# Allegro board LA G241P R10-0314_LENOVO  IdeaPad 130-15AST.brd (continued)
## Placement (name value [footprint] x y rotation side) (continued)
PC9029  22U_0603_6.3V6M  [C_0603]  125.69 50 225 top
PC9030  22U_0603_6.3V6M  [C_0603]  90.1 62.56 270 top
PC9031  22U_0603_6.3V6M  [C_0603]  91.3 61.46 90 top
PC9033  22U_0603_6.3V6M  [C_0603]  92.57 61.46 90 top
PC9034  22U_0603_6.3V6M  [C_0603]  93.65 61.58 0 top
PC9038  22U_0603_6.3V6M  [C_0603]  93.98 60.05 0 top
PC9039  22U_0603_6.3V6M  [C_0603]  94.02 54.01 0 top
PC9040  22U_0603_6.3V6M  [C_0603]  98.36 53.95 180 top
PC9041  22U_0603_6.3V6M  [C_0603]  98.36 56.05 180 top
PC9042  22U_0603_6.3V6M  [C_0603]  98.36 57.95 180 top
PC9043  22U_0603_6.3V6M  [C_0603]  123.79 40.73 90 top
PC9044  22U_0603_6.3V6M  [C_0603]  123.79 36.86 270 top
PC9045  22U_0603_6.3V6M  [C_0603]  125 36.86 270 top
PC9056  22U_0603_6.3V6M  [C_0603]  92.97 60.02 180 top
PC9057  22U_0603_6.3V6M  [C_0603]  124.81 50.89 225 top
PC9058  22U_0603_6.3V6M  [C_0603]  128.39 47.33 225 bottom
PC9059  22U_0603_6.3V6M  [C_0603]  128.4 47.32 225 top
PC9060  22U_0603_6.3V6M  [C_0603]  126.62 49.1 225 top
PC9062  22U_0603_6.3V6M  [C_0603]  127.5 48.21 225 bottom
PC9063  22U_0603_6.3V6M  [C_0603]  126.61 49.1 225 bottom
PC9064  10U_0402_6.3V6M  [C_0402]  100.38 54.14 90 top
PC9065  10U_0402_6.3V6M  [C_0402]  101.48 52.77 270 top
PC9067  22U_0603_6.3V6M  [C_0603]  125 40.73 90 top
PC9068  22U_0603_6.3V6M  [C_0603]  123.79 36.86 270 bottom
PC9070  22U_0603_6.3V6M  [C_0603]  123.79 40.73 90 bottom
PC9071  22U_0603_6.3V6M  [C_0603]  125 36.86 270 bottom
PC9082  10U_0402_6.3V6M  [C_0402]  98.41 63.72 180 top
PC9084  220U_D2 SX_2VY_R9M  [C_D2]  130.58 54.77 0 bottom
PC9085  560U_2.5V_M  [C_OVH561M0ETR-0606]  119.79 60.2 270 bottom
PC9086  330U_D3_2.5VY_R6M  [C_D3]  125.69 60.52 90 bottom
PC9088  220U_D2 SX_2VY_R9M  [C_D2]  116 37.62 270 bottom
PC9089  220U_D2 SX_2VY_R9M  [C_D2]  120.77 37.62 270 bottom
PC11213  22U_0603_6.3V6M  [C_0603]  125 40.73 90 bottom
PC11214  0.1U_0402_16V7K  [C_0402]  146.65 31.97 180 bottom
PC11215  4.7U_0402_6.3V6M  [C_0402]  145.3 28.48 0 bottom
PC11216  10U_0805_6.3V6M  [C_0805]  146.59 33.3 180 bottom
PC11217  1U_0402_6.3V6K  [C_0402]  152.49 27.28 270 bottom
PC11224  100U_25V_NC_6.3X6  [C_6P3X6]  133.77 28.86 180 bottom
PC11225  22U_0603_6.3V6M  [C_0603]  69.62 23.46 0 top
PC11226  22U_0603_6.3V6M  [C_0603]  69.62 23.46 0 bottom
PC11227  0.1U_0402_25V6  [C_0402]  51.07 112.02 0 bottom
PD101  S SCH DIO BAS40CW SOT-323  [RB715F_SOT323-3]  25.47 16.29 270 bottom
PD501  30MA_30V_0.5UA_0.4V_SOD323-2  [D_SOD323-2]  39.15 117.82 0 top
PD703  -  [LRB715FT1G_SOT323-3]  139.32 13.31 0 bottom
PF101  7A_32VDC_0437007.WRML  [F_1206]  16.91 146.4 0 top
PF201  F1206HB12V024TM 12A 24V UL FAST  [F_1206]  108.17 26.71 0 bottom
PH201  100K +-1% 0402 B25/50 4250K  [R_0402]  98.07 66.59 270 top
PH801  100K_0402_1%_B25/50 4250K  [R_0402]  135.93 34.57 180 bottom
PH802  100K_0402_1%_B25/50 4250K  [R_0402]  145.63 49.7 270 bottom
PH803  100K_0402_1%_B25/50 4250K  [R_0402]  133.43 51.85 0 bottom
PH804  100K_0402_1%_B25/50 4250K  [R_0402]  126.14 33.94 180 bottom
PH1001  100K_0402_1%_B25/50 4250K  [R_0402]  74.46 102.14 180 bottom
PH1002  100K_0402_1%_B25/50 4250K  [R_0402]  62.51 102.98 270 bottom
PJ401  -  [JUMP_43X118]  158.33 12.26 270 bottom
PJ403  -  [JUMP_43X118]  166.21 12.77 270 bottom
PJ501  -  [JUMP_43X118]  29.62 101.42 270 bottom
PJ502  -  [JUMP_43X118]  34.83 101.42 270 bottom
PJ503  -  [JUMP_43X39]  30.52 112.87 180 bottom
PJ601  -  [JUMP_43X118]  67.72 25.64 90 bottom
PJ602  -  [JUMP_43X79]  72.99 16.56 90 top
PJ801  -  [JUMP_43X79]  77.03 9.49 180 top
PJ802  -  [JUMP_43X79]  62.7 8.92 180 top
PJ803  -  [JUMP_43X79]  53.14 5.14 90 top
PJ804  -  [JUMP_43X79]  53.56 19.42 90 top
PJ901  -  [JUMP_43X118]  41.07 154.59 0 top
PJ902  -  [JUMP_43X118]  49.01 155.16 0 bottom
PJ1000  -  [JUMP_43X39]  151.3 27.02 180 bottom
PJ1001  -  [JUMP_43X39]  150.38 34.76 0 bottom
PJP402  -  [JUMP_43X39]  161.65 20.88 0 top
PJP404  -  [JUMP_43X39]  169.56 21.94 270 top
PL101  5A_Z120_25M_0805_2P  [TAI-T_HCB2012KF-121T50_2P]  17.31 148.23 90 top
PL102  5A_Z120_25M_0805_2P  [TAI-T_HCB2012KF-121T50_2P]  19.15 148.23 90 top
PL201  5A_Z120_25M_0805_2P  [TAI-T_HCB2012KF-121T50_2P]  112.4 27.97 0 bottom
PL202  5A_Z120_25M_0805_2P  [TAI-T_HCB2012KF-121T50_2P]  112.4 26.19 0 bottom
PL301  1UH_2.8A_30%_4X4X2_F  [L_4X4X2_F_2P]  131.73 24.35 270 bottom
PL401  5A_Z120_25M_0805_2P  [5A_Z120_0805_2P]  153.42 23.59 0 bottom
PL402  1.5UH_6A_20%_5X5X3_M  [L_5X5X3_M]  157.99 19.76 270 bottom
PL403  5A_Z120_25M_0805_2P  [5A_Z120_0805_2P]  162.84 28.57 270 bottom
PL404  1.5UH_6A_20%_5X5X3_M  [L_5X5X3_M]  166.07 20.26 270 bottom
PL501  5A_Z120_25M_0805_2P  [5A_Z120_0805_2P]  38.61 100.93 0 bottom
PL502  1UH_11A_20%_7X7X3_M  [L_7X7X3_M]  32.41 106.47 0 bottom
PL602  1UH_6.6A_20%_5X5X3_M  [L_5X5X3_M_2P]  68.67 16.67 90 bottom
PL700  4.7UH_5.5A_20%_7X7X3_M  [L_7X7X3_M_2P]  129 12.75 90 bottom
PL801  -  [5A_Z80_0805_2P]  137.21 26.07 180 bottom
PL802  -  [5A_Z80_0805_2P]  137.21 24.29 180 bottom
PL803  0.24UH_22A_+-20%_ 7X7X3_M  [L_7X7X3_M]  137.06 47.59 180 bottom
PL804  0.24UH_22A_+-20%_ 7X7X3_M  [L_7X7X3_M]  133.57 38.32 180 bottom
PL901  1UH_6.6A_20%_5X5X3_M  [L_5X5X3_M_2P]  44.78 148.22 90 bottom
PL1001  0.24UH_22A_+-20%_ 7X7X3_M  [L_7X7X3_M]  70.04 106.37 0 bottom
PL1002  -  [5A_Z80_0805_2P]  64.12 112.93 180 bottom
PQ501  -  [AON7408L_DFN8-5]  38.76 104.74 180 top
PQ502  -  [AON7506_DFN3X3-8-5]  39.65 106.65 90 top
PQ704  -  [AON7408L_DFN8-5]  136.77 18.52 180 bottom
PQ705  -  [AON7506_DFN33-8-5]  125.8 20.95 180 bottom
PQ706  -  [AON7752_DFN3X3EP8-5]  137.65 16.61 270 bottom
PQ707  -  [2N7002KW_SOT323-3]  30.67 156.44 270 top
PQ710  -  [LMUN5113T1G_SOT323-3]  124.57 12.43 270 bottom
PQ711  -  [LTC015EUBFS8TL_UMT3F]  120.74 11.55 0 bottom
PQ712  -  [AON7506_DFN33-8-5]  28.05 154.42 270 top
PQ740  -  [EMB04N03H_EDFN5X6-8-5]  25.93 152.86 90 top
PQ741  -  [L2N7002WT1G_SC70-3]  141.76 11.41 180 bottom
PQ801  -  [AON6380_DFN5X6-8-5]  145.9 51.21 90 bottom
PQ802  AON6314_N_DFN56-8-5  [Q_N_DFN56-8-5]  143.92 47.08 180 bottom
PQ803  -  [AON6380_DFN5X6-8-5]  137.57 34.44 0 bottom
PQ804  AON6314_N_DFN56-8-5  [Q_N_DFN56-8-5]  141.89 40.29 270 bottom
PQ1001  -  [AON6962_DFN5X6D-8-7]  63.4 110.31 0 bottom
PR107  45.3K_0603_1%  [R_0603]  22.38 15.4 90 bottom
PR108  1.5K_0603_5%  [R_0603]  21.17 15.52 180 bottom
PR109  1K_0603_5%  [R_0603]  21.17 16.79 180 bottom
PR201  100_0402_1%  [R_0402]  110.71 29.56 90 top
PR202  100_0402_1%  [R_0402]  109.88 29.56 90 top
PR203  200K_0402_1%  [R_0402]  112.93 29.56 90 top
PR204  200K_0402_1%  [R_0402]  112.11 29.56 90 top
PR205  10K_0402_5%  [R_0402]  113.76 29.56 90 top
PR206  16.5K_0402_1%  [R_0402]  159.84 64.23 0 top
PR401  0_0402_5%  [R0402_0OHM]  156.21 22.9 270 bottom
PR402  499K_0402_1%  [R_0402]  161.32 27.92 270 bottom
PR403  1K_0402_1%  [R_0402]  162.92 22.83 180 top
PR404  150K_0402_1%  [R_0402]  160.49 27.01 90 bottom
PR405  4.7_1206_5%  [R_1206]  156.68 23.4 270 top
PR406  100K_0402_5%  [R_0402]  159.51 28.01 270 bottom
PR407  1K_0402_1%  [R_0402]  171.06 26.81 90 bottom
PR408  0_0402_5%  [R0402_0OHM]  165.41 23.64 270 bottom
PR409  4.7_1206_5%  [R_1206]  165.06 20.73 0 top
PR410  2.2K_0402_5%  [R_0402]  167.67 36.3 270 top
PR411  0_0402_5%  [R0402_0OHM]  166.91 36.3 270 top
PR412  1M_0402_1%  [R_0402]  162 24.6 0 top
PR451  560K_0402_5%  [R_0402]  164.73 30.45 0 top
PR452  105K_0402_1%  [R_0402]  165.65 31.27 180 top
PR501  2.2_0603_5%  [R_0603]  38.51 110.96 180 bottom
PR502  12.7K_0402_1%  [R_0402]  40.74 114.08 180 bottom
PR503  4.7_1206_5%  [R_1206]  36.79 110.52 0 top
PR504  5.1_0603_5%  [R_0603]  41.11 116.3 180 bottom
PR505  2.2_0603_5%  [R_0603]  41.11 116.3 180 top
PR506  6.04K_0402_1%  [R_0402]  33.49 116.63 270 bottom
PR507  470K_0402_1%  [R_0402]  38.51 115.59 90 top
PR508  0_0402_5%  [R0402_0OHM]  37.89 118.78 180 top
PR509  10K_0402_1%  [R_0402]  32.62 116.62 180 bottom
PR510  0_0402_5%  [R0402_0OHM]  36.1 118.79 270 top
PR601  1M_0402_1%  [R_0402]  63.27 20.15 90 bottom
PR603  0_0402_5%  [R0402_0OHM]  62.45 21.06 270 bottom
PR605  4.7_1206_5%  [R_1206]  72.61 15.59 90 bottom
PR606  0_0402_5%  [R0402_0OHM]  68.91 15.84 0 top
PR607  0_0402_5%  [R0402_0OHM]  62.05 19 0 top
PR608  12.1K_0402_1%  [R_0402]  62.18 16.34 0 top
PR609  0_0402_5%  [R_0402]  62.97 19.89 180 top
PR610  20K_0402_1%  [R_0402]  62.97 18.12 180 top
PR611  100K_0402_5%  [R_0402]  64.1 20.1 0 top
PR612  1K_0402_1%  [R_0402]  62.19 17.16 0 top
PR703  0.01_1206_1%  [R_1206_4P]  32.13 153.99 0 top
PR727  10K_0402_1%  [R_0402]  152.47 15.26 0 bottom
PR729  287K_0402_1%  [R_0402]  151.74 22.19 180 bottom
PR731  158K_0402_1%  [R_0402]  152.49 19.68 0 bottom
PR732  49.9K_0402_1%  [R_0402]  150.83 21.43 0 bottom
PR737  3M_0402_5%  [R_0402]  33.73 156.4 90 top
PR738  1M_0402_1%  [R_0402]  34.63 155.59 180 top
PR740  2_0402_5%  [R_0402]  149.08 22.37 270 bottom
PR741  100K_0402_1%  [R_0402]  153.41 18.79 180 bottom
PR742  2_0402_5%  [R_0402]  145.51 13.05 270 bottom
PR743  10_1206_5%  [R_1206]  142.46 14.99 180 bottom
PR745  100_0402_1%  [R_0402]  145.8 20.9 90 bottom
PR749  200K_0402_1%  [R_0402]  143.74 13.23 0 bottom
PR750  200K_0402_1%  [R_0402]  149.95 12.13 90 bottom
PR751  76.8K_0402_1%  [R_0402]  144.6 12.29 180 bottom
PR752  162K_0402_1%  [R_0402]  150.78 13.05 270 bottom
PR753  165K_0402_1%  [R_0402]  152.47 14.37 0 bottom
PR754  499_0402_1%  [R_0402]  151.6 13.51 270 bottom
PR755  38.3K_0402_1%  [R_0402]  149.06 13.05 270 bottom
PR757  100K_0402_1%  [R_0402]  144.81 15.09 270 bottom
PR760  4.7_0402_5%  [R_0402]  143.58 16.43 90 bottom
PR762  4.02K_0402_1%  [R_0402]  28.08 156.75 0 top
PR763  4.02K_0402_1%  [R_0402]  28.08 155.92 0 top
PR765  0.01_1206_1%  [R_1206_4P]  124.61 15.33 180 bottom
PR766  4.7_1206_5%  [R_1206]  133.44 12.41 0 bottom
PR769  0_0402_5%  [R0402_0OHM]  153.39 17.92 180 bottom
PR770  0_0402_5%  [R0402_0OHM]  153.39 17.04 180 bottom
PR771  0_0603_5%  [R0603_0OHM]  144.87 20.72 180 bottom
PR772  0_0402_5%  [R0402_0OHM]  149.88 22.36 270 bottom
PR776  0_0402_5%  [R0402_0OHM]  147.3 12.15 180 bottom
PR777  0_0402_5%  [R0402_0OHM]  153.39 16.15 180 bottom
PR778  10K_0402_1%  [R_0402]  148.17 13.05 270 bottom
PR779  76.8K_0402_1%  [R_0402]  143.69 11.41 0 bottom
PR780  1K_0402_1%  [R_0402]  160.05 65.17 90 top
PR801  1_0402_5%  [R_0402]  148.69 43.45 90 bottom
PR803  2.2_0603_5%  [R_0603]  150.78 45.62 180 bottom
PR804  4.7_1206_5%  [R_1206]  135.98 42.83 0 bottom
PR805  1.91K_0603_1%  [R_0603]  153.75 49.04 0 bottom
PR806  4.7_0805_5%  [R_0805]  150.69 38.7 0 top
PR807  48.7K_0402_1%  [R_0402]  154.22 47.85 180 top
PR808  0_0402_5%  [R0402_0OHM]  156.05 36.62 270 top
PR809  10K_0402_1%  [R_0402]  155.98 48.75 270 top
PR810  45.3K_0402_1%  [R_0402]  153.88 40.99 0 top
PR811  10K_0402_1%  [R_0402]  154.26 38.38 0 top
PR812  10_0402_1%  [R_0402]  155.23 36.61 180 top
PR813  100K_0402_5%  [R_0402]  152.03 47.85 0 bottom
PR814  0_0402_5%  [R0402_0OHM]  156 49.56 180 top
PR816  10_0402_1%  [R_0402]  156.94 48.75 270 top
PR818  2.2_0402_5%  [R_0402]  156.67 40.29 0 top
PR820  10_0402_1%  [R_0402]  158.27 37.29 90 top
PR821  60.4K_0402_1%  [R_0402]  155.86 38.84 270 bottom
PR823  10_0402_1%  [R_0402]  154.14 45.42 90 top
PR824  0_0402_5%  [R0402_0OHM]  157.44 38.84 270 bottom
PR825  316K_0402_1%  [R_0402]  157.51 36.62 270 bottom
PR826  0_0402_5%  [R0402_0OHM]  158.33 35.7 90 bottom
PR827  0_0402_5%  [R0402_0OHM]  153.3 49.56 0 top
PR828  24K_0402_1%  [R_0402]  156.11 36.62 270 bottom
PR829  0_0402_5%  [R0402_0OHM]  92.23 73.04 90 bottom
PR830  60.4K_0402_1%  [R_0402]  159.34 45.12 0 bottom
PR831  0_0402_5%  [R0402_0OHM]  159.08 45.18 0 top
PR832  169K_0402_1%  [R_0402]  159.92 45.99 90 top
PR833  0_0402_5%  [R0402_0OHM]  92.23 75.74 270 bottom
PR834  25.5K_0402_1%  [R_0402]  159.34 46.89 0 bottom
PR835  100K_0402_5%  [R_0402]  160.24 40.37 270 bottom
PR836  15.4K_0402_1%  [R_0402]  156.8 44.61 0 top
PR837  2.2_0402_5%  [R_0402]  158.89 41.88 0 top
PR838  0_0402_5%  [R0402_0OHM]  159.11 46 180 top
PR839  34.8K_0402_1%  [R_0402]  157.06 46.4 270 top
PR841  2.2_0603_5%  [R_0603]  150.71 39.72 180 bottom
PR842  8.45K_0402_1%  [R_0402]  159.34 41.81 0 bottom
PR843  15K_0402_1%  [R_0402]  159.34 44.29 0 bottom
PR844  4.7_1206_5%  [R_1206]  133.7 33.49 180 bottom
PR845  1.13K_0402_1%  [R_0402]  152.54 36.61 0 bottom
PR846  17.4K_0402_1%  [R_0402]  160 44.35 180 top
PR847  15K_0402_1%  [R_0402]  160.25 42.64 180 bottom
PR848  9.1K_0402_1%  [R_0402]  160 43.53 180 top
PR849  12K_0402_1%  [R_0402]  159.34 43.46 0 bottom
PR850  3.9_0402_1%  [R_0402]  157.7 43.73 270 top
PR851  0_0402_5%  [R0402_0OHM]  151.92 37.86 90 bottom
PR852  806_0402_1%  [R_0402]  156.1 48.8 0 bottom
PR853  1.13K_0402_1%  [R_0402]  154.13 37.5 0 bottom
PR901  0_0402_5%  [R0402_0OHM]  45.65 148.93 90 top
PR902  150K_0402_1%  [R_0402]  40.73 142.73 270 top
PR903  1M_0402_1%  [R_0402]  41.57 143.54 180 top
PR904  4.7_1206_5%  [R_1206]  45.37 145.38 180 bottom
PR905  22.6K_0402_1%  [R_0402]  45.7 143.1 180 top
PR906  0_0402_5%  [R_0402]  42.49 142.98 270 top
PR907  18K_0402_1%  [R_0402]  43.38 142.98 270 top
PR1001  3.9_0402_1%  [R_0402]  51.26 108.62 0 bottom
PR1002  100K_0402_1%  [R_0402]  57.7 112.32 180 top
PR1003  187K_0402_1%  [R_0402]  51.26 104.49 0 bottom
PR1004  0_0402_5%  [R0402_0OHM]  52.56 105.31 180 bottom
PR1005  0_0402_5%  [R0402_0OHM]  55.08 112.31 270 top
PR1006  4.7K_0402_1%  [R_0402]  51.06 113.76 0 bottom
PR1007  0_0402_5%  [R0402_0OHM]  49.48 106.14 0 bottom
PR1008  14.3K_0402_1%  [R_0402]  52.56 106.96 180 top
PR1009  10.5K_0402_1%  [R_0402]  51.26 106.96 0 bottom
PR1010  59K_0402_1%  [R_0402]  51.64 105.31 0 top
PR1011  10.2K_0402_1%  [R_0402]  52.17 107.79 180 bottom
PR1012  68K_0402_1%  [R_0402]  51.64 106.14 0 top
PR1013  13K_0402_1%  [R_0402]  51.64 106.14 0 bottom
PR1014  0_0402_5%  [R0402_0OHM]  56.28 103.47 0 top
PR1015  47K_0402_1%  [R_0402]  59.71 104.74 0 bottom
PR1016  4.7K_0402_1%  [R_0402]  52.17 103.66 180 bottom
PR1017  10K_0402_1%  [R_0402]  57.32 101.06 180 bottom
PR1018  0_0402_5%  [R0402_0OHM]  54.19 112.44 270 bottom
PR1019  10_0402_5%  [R_0402]  58.96 104.41 90 top
PR1020  931_0402_1%  [R_0402]  55.29 102.71 180 bottom
PR1021  0_0402_5%  [R0402_0OHM]  50.38 104.48 90 bottom
PR1022  0_0402_5%  [R0402_0OHM]  53.3 112.44 270 bottom
PR1023  300_0402_1%  [R_0402]  48.67 106.15 270 bottom
PR1024  0_0402_5%  [R0402_0OHM]  56.28 102.58 0 top
PR1025  0_0402_5%  [R0402_0OHM]  55.03 112.44 270 bottom
PR1026  34K_0402_1%  [R_0402]  49.56 105.39 270 bottom
PR1027  10_0402_5%  [R_0402]  58.94 102.58 0 top
PR1028  76.8K_0402_1%  [R_0402]  56.4 102.71 0 bottom
PR1029  4.7_0603_5%  [R_0603]  52.07 110.9 180 bottom
PR1030  1.37K_0603_1%  [R_0603]  55.08 100.42 90 bottom
PR1031  2.2_0603_5%  [R_0603]  57.27 111.12 0 bottom
PR1032  4.7_0603_5%  [R_0603]  60.8 103.66 180 bottom
PR1033  0_0603_5%  [R0603_0OHM]  59.65 106.77 0 bottom
PR1034  4.7_1206_5%  [R_1206]  70.51 101.57 180 bottom
PR1098  0_0402_5%  [R_0402]  56.78 111.51 180 top
PR1099  10K_0402_5%  [R_0402]  51.06 112.92 0 bottom
PR1458  3.24K_0402_1%  [R_0402]  146.2 29.35 90 bottom
PR1459  1K_0402_1%  [R_0402]  146.65 31.08 180 bottom
PR2001  12.7K_0402_1%  [R_0402]  65.37 8.03 270 top
PR2002  1.6K_0402_1%  [R_0402]  51.18 17.93 270 top
PR2003  0_0402_5%  [R0402_0OHM]  50.38 7.83 90 top
PR2004  3.4K_0402_1%  [R_0402]  52.94 17.94 180 top
PR2005  0_0402_5%  [R0402_0OHM]  75.66 6.24 90 top
PR2006  1M_0402_5%  [R_0402]  74.83 7.16 270 top
PR2007  10K_0402_1%  [R_0402]  65.37 6.32 270 top
PR2008  47K_0402_5%  [R_0402]  51.21 8.74 270 top
PR2009  100K_0402_5%  [R_0402]  73.07 5.17 180 top
PR2221  10_0402_1%  [R_0402]  61.36 15.37 0 top
PR2222  0_0402_1%  [R_0402]  62.27 14.55 180 top
PR2223  0_0402_5%  [R_0402]  49.57 7.83 90 top
PU401  -  [SY8286BRAC_QFN20_3X3]  157.46 23.1 0 bottom
PU402  -  [SY8286CRAC_QFN20_3X3]  166.65 23.76 0 bottom
PU501  -  [RT8207PGQW_WQFN20_3X3]  35.04 113.91 90 bottom
PU601  -  [SY8288RAC_QFN20_3X3]  67.55 16.15 180 top
PU703  S IC ISL88739AHRZ-T QFN 32P CHARGER  [ISL95520HRZ-T_QFN32_4X4]  150.22 18.39 180 bottom
PU801  -  [RT3661ABGQW_WQFN40_5X5]  152.87 45.67 270 bottom
PU901  -  [SY8286RAC_QFN20_3X3]  45.35 147.57 270 top
PU903  G2992F1U  [APL5336KAI-TRL_SOP8P8]  148.36 28.99 90 bottom
PU1001  -  [RT3662EBGQW_WQFN32_4X4]  57.54 105.38 90 bottom
PU2001  -  [G9661MF11U_SO8]  72.35 6.38 90 top
PU2002  -  [G9661MF11U_SO8]  50.75 10.23 0 top
Q19  ME4856-G_SO8  [AO4430L_SO8]  69.6 34.41 180 top
Q83  2N7002KW_SOT323-3  [L2N7002WT1G_SC-70-3]  60.61 29.81 0 top
Q84  -  [2N7002KW_SOT323-3]  63.27 29.81 180 top
Q201  -  [PJ2301_SOT23-3]  26.04 143.6 270 top
Q401  -  [2N7002KDW_SOT363-6]  59.82 4.46 90 top
Q411  -  [2N7002K_SOT23-3]  29.17 114.75 0 top
Q412  -  [2N7002K_SOT23-3]  33.17 114.75 0 top
QC1  -  [LBSS139WT1G_SC70-3]  93.06 71.4 0 top
QC2  PJT138KA_SOT363-6  [DMN66D0LDW-7_SOT363-6]  82.96 86.28 270 bottom
QC17  -  [PJT138KA_SOT363-6]  90.39 27.73 270 bottom
QC18  AO3416L_SOT23-3  [AO3416_SOT23-3]  151.03 28.31 180 top
QC19  AO3416L_SOT23-3  [AO3416_SOT23-3]  151.03 33.01 180 top
QC20  AO3416L_SOT23-3  [AO3416_SOT23-3]  155.03 28.31 180 top
QC21  AO3416L_SOT23-3  [AO3416_SOT23-3]  155.03 33.01 180 top
QC22  2N7002KDW_SOT-363-6  [DMN66D0LDW-7_SOT363-6]  145.45 25.42 90 bottom
QH5  -  [MMBT3904_NL_SOT23-3]  24.6 110.23 0 bottom
QH15  2N7002KDW 2N SC88-6  [2N7002DW-T-R7_SOT363-6]  19.49 107.46 90 bottom
QH17  -  [2N7002KW_SOT323-3]  18.19 98.16 180 top
QV1  L2N7002SDW1T1G 2N SOT-363  [2N7002KDWH_SOT363-6]  87.8 147.92 270 top
QV11  -  [2N7002KW_SOT323-3]  83.09 107.79 0 top
QV16  -  [PJ2301_SOT23-3]  102.39 103.5 180 top
QV17  -  [2N7002KW_SOT323-3]  99.38 104.61 90 top
QV18  -  [2N7002KW_SOT323-3]  97.56 102.68 180 top
QV21  L2N7002DW1T1G 2N SOT-363  [2N7002KDW_SOT363-6]  82.5 111.18 0 top
R189  0_0603_5%  [R0603_0OHM]  177.7 46.39 180 top
R192  47K_0402_5%  [R_0402]  176.1 67.21 0 top
R194  10K_0402_5%  [R_0402]  159.51 61.22 180 top
R198  10K_0402_5%  [R_0402]  160.94 54.31 90 top
R201  150K_0402_5%  [R_0402]  30.61 144 270 top
R202  100K_0402_5%  [R_0402]  33.54 145.89 0 top
R203  0_0805_5%  [R0805_0OHM]  37.34 151.61 0 top
R204  0_0402_5%  [R0402_0OHM]  25.21 146.74 90 top
R205  100K_0402_5%  [R_0402]  24.39 146.74 90 top
R207  0_0402_5%  [R0402_0OHM]  26.94 149.19 0 top
R209  100K_0402_5%  [R_0402]  26.94 150.02 0 top
R210  100K_0402_5%  [R_0402]  24.35 145.93 0 top
R211  0_0805_5%  [R0805_0OHM]  30.06 149.42 90 top
R212  0_0603_5%  [R0603_0OHM]  25.19 141.47 180 top
R214  10K_0402_5%  [R_0402]  180.05 62.02 270 top
R233  0_0805_5%  [R0805_0OHM]  176.2 21.95 0 bottom
R242  0_0805_5%  [R0805_0OHM]  163.26 40.95 0 top
R243  0_0402_5%  [R0402_0OHM]  173.7 42.33 270 top
R244  0_0402_5%  [R0402_0OHM]  174.53 42.33 270 top
R245  0_0402_5%  [R0402_0OHM]  175.41 42.33 270 top
R246  0_0402_5%  [R0402_0OHM]  175.73 34.11 90 bottom
R247  0_0402_5%  [R0402_0OHM]  177.5 42.63 0 top
R248  0_0402_5%  [R0402_0OHM]  177.5 43.46 0 top
R249  0_0402_5%  [R_0402]  176.62 34.11 90 bottom
R250  0_0402_5%  [R0402_0OHM]  177.5 41.81 0 top
R251  100K_0402_5%  [R_0402]  172.94 41.41 90 top
R271  0_0402_5%  [R_0402]  131.87 63.47 180 top
R272  470_0402_5%  [R_0402]  157.55 56.27 180 top
R273  100K_0402_5%  [R_0402]  9.31 156.63 90 top
R274  470_0402_5%  [R_0402]  132.74 63.54 270 top
R275  0_0402_5%  [R0402_0OHM]  150.82 62.12 270 top
R276  0_0402_5%  [R0402_0OHM]  151.6 62.12 270 top
R277  470_0402_5%  [R_0402]  152.89 62.13 270 top
R278  0_0402_5%  [R0402_0OHM]  131.87 62.64 180 top
R279  0_0805_5%  [R0805_0OHM]  172.85 22.47 270 bottom
R280  4.7K_0402_5%  [R_0402]  174.18 21.89 270 bottom
R283  0_0402_5%  [R0402_0OHM]  157.55 57.03 180 top
R301  0_0402_5%  [R_0402]  22.62 66.96 0 bottom
R364  16.5K_0402_1%  [R_0402]  118.26 12.17 270 bottom
R365  16.5K_0402_1%  [R_0402]  158.66 64.74 180 top
R366  100K +-1% 0402 B25/50 4250K  [R_0402]  119.09 11.26 90 bottom
R367  100K +-1% 0402 B25/50 4250K  [R_0402]  49.61 117.38 0 bottom
R368  16.5K_0402_1%  [R_0402]  127.92 43.6 270 bottom
R369  100K +-1% 0402 B25/50 4250K  [R_0402]  128.74 42.69 90 bottom
R371  0_0603_5%  [R0603_0OHM]  104.07 97.27 180 bottom
R376  200_0402_1%  [R_0402]  7.22 136.62 0 bottom
R377  412_0402_1%  [R_0402]  31.07 3.84 0 top
R378  200_0402_1%  [R_0402]  7.22 137.44 0 bottom
R420  0_0805_5%  [R0805_0OHM]  182.65 64.83 270 top
R428  0_0402_5%  [R0402_0OHM]  180.11 64.72 90 top
R921  10_0402_5%  [R_0402]  180.42 55.53 0 top
R922  0_0402_5%  [R0402_0OHM]  166.12 47.16 180 top
R923  0_0402_5%  [R0402_0OHM]  166.91 47.27 270 top
R929  0_0402_5%  [R0402_0OHM]  165.2 46.39 0 top
R930  4.7K_0402_5%  [R_0402]  168.75 44.75 0 top
R931  10K_0402_5%  [R_0402]  167.9 47.24 270 top
R932  0_0402_5%  [R0402_0OHM]  174.45 46.51 0 top
R933  470_0402_5%  [R_0402]  29.87 112.03 90 top
R934  100K_0402_5%  [R_0402]  33.7 118.52 180 top
R935  470_0603_5%  [R_0603]  68.13 36.37 180 top
R937  0_0402_5%  [R0402_0OHM]  87.01 29.37 0 top
R940  0_0402_5%  [R0402_0OHM]  91.84 31.65 0 top
R941  0_0402_5%  [R_0402]  87.01 30.19 0 top
R944  100K_0402_5%  [R_0402]  144.49 26.27 270 bottom
R945  100K_0402_1%  [R_0402]  57.11 6.01 270 top
R946  22_0603_1%  [R_0603]  59.84 8.22 270 top
R947  4.7K_0402_5%  [R_0402]  62.75 31.02 0 top
R948  100K_0402_5%  [R_0402]  160.24 49.87 90 top
R949  100K_0402_5%  [R_0402]  163.11 47.99 0 top
R950  0_0402_5%  [R0402_0OHM]  117.8 46.69 90 bottom
R951  0_0402_5%  [R0402_0OHM]  116.91 46.69 90 bottom
RA2  0_0805_5%  [R0805_0OHM]  13.21 15.78 0 bottom
RA6  0_0603_5%  [R0603_0OHM]  2.4 22.78 270 bottom
RA23  200K_0402_1%  [R_0402]  7.36 29.72 90 bottom
RA31  BLM15BD121SN1D_2P  [MURAT_BLM15BD121SN1D_2P]  19.71 49.1 270 bottom
RA36  4.7K_0402_5%  [R_0402]  18.24 44.54 0 bottom
RA41  47K_0402_5%  [R_0402]  9.35 36.73 0 bottom
RA42  BLM15BD121SN1D_2P  [MURAT_BLM15BD121SN1D_2P]  16.41 47.32 270 bottom
RA43  10K_0402_5%  [R_0402]  16.72 15.59 0 bottom
RA44  10K_0402_5%  [R_0402]  17.44 45.37 180 bottom
RA45  47_0402_5%  [R_0402]  19.95 43.65 0 bottom
RA46  0_0402_5%  [R0402_0OHM]  16.72 16.41 0 bottom
RA47  27K_0402_5%  [R_0402]  9.48 33.75 0 bottom
RA48  0_0603_5%  [R0603_0OHM]  17.38 29.8 315 bottom
RA49  4.7K_0402_5%  [R_0402]  17.44 44.54 180 bottom
RA50  33_0402_5%  [R_0402]  5.4 23.76 180 bottom
RA51  100K_0402_1%  [R_0402]  6.61 30.08 180 bottom
RA52  33_0402_5%  [R_0402]  4.96 25.95 180 bottom
RA53  0_0402_5%  [R0402_0OHM]  13.17 18.39 270 bottom
RA54  2.2K_0402_5%  [R_0402]  9.14 30.63 270 bottom
RA55  47K_0402_5%  [R_0402]  9.35 35.91 0 bottom
RA56  47_0402_5%  [R_0402]  16.53 43.74 0 bottom
RA57  10K_0402_5%  [R_0402]  18.24 45.37 0 bottom
RA58  2.2K_0402_5%  [R_0402]  8.25 30.63 270 bottom
RA59  0_0603_5%  [R0603_0OHM]  3.65 19.84 180 bottom
RA60  0_0402_5%  [R0402_0OHM]  4.46 29.09 0 bottom
RA61  0_0402_5%  [R0402_0OHM]  13.57 52.53 270 bottom
RA62  33K_0402_5%  [R_0402]  16.65 48.16 0 bottom
RA63  0_0402_5%  [R0402_0OHM]  19.76 37.9 180 bottom
RA64  0_0402_5%  [R0402_0OHM]  18.24 42.77 0 bottom
RA65  0_0402_5%  [R0402_0OHM]  21.24 49.76 225 top
RA66  0_0402_5%  [R0402_0OHM]  4.46 28.22 0 bottom
RC1  196_0402_1%  [R_0402]  102.58 55.26 90 top
RC2  196_0402_1%  [R_0402]  105.43 55.15 0 top
RC3  39.2_0402_1%  [R_0402]  78.02 53.56 180 bottom
RC4  1K_0402_5%  [R_0402]  77.1 57.82 0 bottom
RC13  300_0402_5%  [R_0402]  96.42 75.42 270 bottom
RC14  300_0402_5%  [R_0402]  89.94 76.31 270 top
RC16  150_0402_1%  [R_0402]  95.23 65.88 180 top
RC17  2K_0402_1%  [R_0402]  96.36 68.92 90 bottom
RC18  2.2K_0402_5%  [R_0402]  94.13 79.77 90 bottom
RC20  0_0402_5%  [R0402_0OHM]  94.77 73.11 90 bottom
RC21  4.7K_0402_5%  [R_0402]  95.15 83.42 270 top
RC22  100K_0402_5%  [R_0402]  93.69 68.31 270 top
RC24  4.7K_0402_5%  [R_0402]  93.23 80.61 0 top
RC25  1K_0402_5%  [R_0402]  92.42 67.45 90 top
RC26  1K_0402_5%  [R_0402]  92.42 66.59 270 top
RC27  33_0402_5%  [R_0402]  84.13 80.92 90 top
RC30  0_0402_5%  [R_0402]  79.72 88.54 90 bottom
RC34  2.2K_0402_5%  [R_0402]  112.37 51.85 180 bottom
RC35  2.2K_0402_5%  [R_0402]  107.23 53.43 180 top
RC36  1K_0402_5%  [R_0402]  113.68 53.24 0 bottom
RC38  15K_0402_5%  [R_0402]  112.37 51.02 180 bottom
RC39  15K_0402_5%  [R_0402]  114.59 52.42 180 bottom
RC40  15K_0402_5%  [R_0402]  105.56 53.89 270 top
RC41  10K_0402_5%  [R_0402]  98.96 28.53 90 top
RC44  10K_0402_5%  [R_0402]  112.37 52.99 180 bottom
RC45  10K_0402_5%  [R_0402]  107.23 54.26 180 top
RC46  10K_0402_5%  [R_0402]  114.59 50 180 bottom
RC49  10K_0402_5%  [R_0402]  105.63 34.24 90 bottom
RC52  10K_0402_5%  [R_0402]  105.63 37.76 270 bottom
RC53  10K_0402_5%  [R_0402]  104.8 37.76 270 bottom
RC54  10K_0402_5%  [R_0402]  104.8 35.16 270 bottom
RC59  0_0402_5%  [R0402_0OHM]  114.4 47.53 180 bottom
RC60  47K_0402_5%  [R_0402]  114.4 46.77 180 bottom
RC63  4.7K_0402_5%  [R_0402]  110.07 42.84 270 bottom
RC64  0_0402_5%  [R0402_0OHM]  110.9 42.84 270 bottom
RC66  0_0402_5%  [R0402_0OHM]  110.7 48.62 90 bottom
RC69  10K_0402_5%  [R_0402]  107.23 52.61 180 top
RC71  33_0402_5%  [R_0402]  85.18 32.43 270 bottom
RC73  0_0402_5%  [R0402_0OHM]  83.92 32.42 180 bottom
RC75  10K_0402_5%  [R_0402]  93.88 37.19 270 bottom
RC76  2K_0402_5%  [R_0402]  93.88 35.48 270 bottom
RC77  10K_0402_5%  [R_0402]  91.71 37.56 0 bottom
RC78  2K_0402_5%  [R_0402]  92.62 38.38 180 bottom
RC79  10K_0402_5%  [R_0402]  93.88 39.07 90 bottom
RC80  2K_0402_5%  [R_0402]  93.06 35.48 270 bottom
RC81  10K_0402_5%  [R_0402]  107.23 51.78 180 top
RC82  2K_0402_5%  [R_0402]  105.56 51.99 270 top
RC83  10K_0402_5%  [R_0402]  106.58 47.39 90 top
RC84  2K_0402_5%  [R_0402]  105.63 48.28 90 top
RC85  10K_0402_5%  [R_0402]  110.58 51.86 270 bottom
RC86  2K_0402_5%  [R_0402]  113.68 51.66 0 bottom
RC87  20M_0402_5%  [R_0402]  110.52 39.29 270 bottom
RC88  1K_0402_1%  [R_0402]  100.43 44.76 180 top
RC89  1K_0402_1%  [R_0402]  99.51 48.12 270 top
RC90  10K_0402_5%  [R_0402]  87.91 36.78 90 top
RC93  33_0402_5%  [R_0402]  89.5 36.4 90 bottom
RC94  100K_0402_5%  [R_0402]  88.79 34.57 0 bottom
RC100  1K_0402_1%  [R_0402]  105.62 55.97 0 top
RC101  1K_0402_1%  [R_0402]  102.66 48.48 180 top
RC102  33_0402_5%  [R_0402]  101.64 22.95 180 bottom
RC103  1M_0402_5%  [R_0402]  110.71 64.81 270 bottom
RC104  33_0402_5%  [R_0402]  110.72 65.56 180 bottom
RC105  33_0402_5%  [R_0402]  109.88 64.11 270 bottom
RC108  11.8K_0402_1%  [R_0402]  103.91 47.58 90 top
RC111  0_0402_5%  [R0402_0OHM]  101.89 35.15 180 top
RC112  10K_0402_5%  [R_0402]  111.67 53.94 180 bottom
RC113  10K_0402_5%  [R_0402]  99.91 35.16 270 top
RC120  0_0402_5%  [R0402_0OHM]  92.9 38.12 90 top
RC129  0_0201_5%  [R0201_0OHM]  99.98 38.93 270 bottom
RC130  0_0201_5%  [R0201_0OHM]  100.61 38.93 270 bottom
RC133  10K_0402_5%  [R_0402]  86.27 36.48 180 top
RC134  10K_0402_5%  [R_0402]  86.27 35.65 180 top
RC144  2.2K_0402_5%  [R_0402]  87.77 25.43 0 bottom
RC145  2.2K_0402_5%  [R_0402]  90.4 25.43 180 bottom
RC146  2.2K_0402_5%  [R_0402]  89.49 28.8 0 bottom
RC147  2.2K_0402_5%  [R_0402]  88.62 28.8 180 bottom
RC150  1K_0402_5%  [R_0402]  146.22 24.35 180 top
RC151  1K_0402_5%  [R_0402]  148 24.35 180 top
RC152  100K_0402_5%  [R_0402]  148.29 26.07 0 bottom
RC153  100K_0402_5%  [R_0402]  146.6 24.41 180 bottom
RC156  10K_0402_5%  [R_0402]  108.27 41.04 270 top
RC157  10K_0402_5%  [R_0402]  108.27 38.42 90 top
RC158  10K_0402_5%  [R_0402]  111.67 55.08 180 bottom
RC159  10K_0402_5%  [R_0402]  111.67 55.91 180 bottom
RC160  10K_0402_5%  [R_0402]  94.91 39.91 180 top
RC161  10K_0402_5%  [R_0402]  94.91 39.08 180 top
RC162  2.2K_0402_5%  [R_0402]  82.18 36.86 0 bottom
RC163  2.2K_0402_5%  [R_0402]  81.38 36.86 180 bottom
RC164  0_0402_5%  [R_0402]  97.94 40.85 270 bottom
RD201  1K_0402_5%  [R_0402]  29.27 61.53 270 top
RD202  10K_0402_5%  [R_0402]  32.54 25.06 270 top
RD203  10K_0402_5%  [R_0402]  31.14 25.06 270 top
RD204  10K_0402_5%  [R_0402]  25.34 44.45 0 bottom
RD205  0_0402_5%  [R0402_0OHM]  32.59 23.33 0 top
RD206  0_0402_5%  [R0402_0OHM]  31.14 23.35 270 top
RD207  0_0402_5%  [R0402_0OHM]  26.25 45.27 180 bottom
RD208  1K_0402_1%  [R_0402]  26.25 49.04 90 bottom
RD209  1K_0402_1%  [R_0402]  25.35 48.23 0 bottom
RD210  0_0402_5%  [R0402_0OHM]  38.7 54.27 270 top
RH27  2.2K_0402_5%  [R_0402]  16.72 108.55 0 top
RH28  2.2K_0402_5%  [R_0402]  16.72 107.73 0 top
RH29  4.7K_0402_5%  [R_0402]  23.84 108.89 270 top
RH30  4.7K_0402_5%  [R_0402]  23.08 108.89 270 top
RH133  150K_0402_5%  [R_0402]  25.63 111.98 180 bottom
RH137  100K_0402_5%  [R_0402]  24.15 106.39 0 bottom
RH138  200K_0402_5%  [R_0402]  22.94 111.98 0 bottom
RL1  0_0603_5%  [R0603_0OHM]  38 137.51 90 top
RL4  0_0402_5%  [R0402_0OHM]  11.52 138.09 270 bottom
RL5  0_0402_5%  [R0402_0OHM]  10.63 138.09 270 bottom
RL6  0_0402_5%  [R0402_0OHM]  9.49 114.83 90 bottom
RL7  0_0402_5%  [R0402_0OHM]  10.31 114.83 90 bottom
RL8  1K_0402_5%  [R_0402]  31.7 138.85 0 top
RL9  2.49K_0402_1%  [R_0402]  38.08 133.76 180 bottom
RL10  15K_0402_5%  [R_0402]  32.62 138.02 180 top
RL11  0_0603_5%  [R_0603]  37.99 139.17 90 bottom
RL17  10K_0402_5%  [R_0402]  35.79 136.86 90 top
RL18  0_0603_5%  [R0603_0OHM]  40.22 132.75 180 bottom
RL19  75_0805_5%  [R_0805]  20.03 135.26 90 top
RP3  2.2K_0804_8P4R_5%  [RP_0804_8P4R]  160.5 57.76 180 top
RP4  100K_0804_8P4R_5%  [RP_0804_8P4R]  169.33 41.94 90 top
RPC1  1K_0804_8P4R_5%  [RP_0804_8P4R]  86.44 74.07 90 bottom
RPC2  1K_0804_8P4R_5%  [RP_0804_8P4R]  96.15 74.14 270 top
RPC3  1K_0804_8P4R_5%  [RP_0804_8P4R]  86.72 91.53 90 top
RPC4  1K_0804_8P4R_5%  [RP_0804_8P4R]  83.16 91.53 90 top
RPC5  10K_0804_8P4R_5%  [RP_0804_8P4R]  86.34 80.42 90 top
RPC6  33_0804_8P4R_5%  [RP_0804_8P4R]  108.54 33.11 90 bottom
RPC9  1K_0804_8P4R_5%  [RP_0804_8P4R]  107.04 37.12 270 bottom
RPC11  10K_0804_8P4R_5%  [RP_0804_8P4R]  95.66 24.43 0 bottom
RPC12  10K_0804_8P4R_5%  [RP_0804_8P4R]  87.65 36.16 90 bottom
RPC13  10K_0804_8P4R_5%  [RP_0804_8P4R]  89.07 36.86 90 top
RPC14  1K_0804_8P4R_5%  [RP_0804_8P4R]  90.84 76.35 180 bottom
RPH1  499_0804_8P4R_1%  [RP_0804_8P4R]  17.41 104.98 0 top
RPH2  499_0804_8P4R_1%  [RP_0804_8P4R]  17.41 101.62 0 top
RPV34  10K_8P4R_5%  [RP_0804_8P4R]  84.3 149.45 270 bottom
RR1  6.19K_0402_1%  [R_0402]  29.99 9.11 0 top
RR5  0_0402_5%  [R0402_0OHM]  23.14 9.19 270 top
RV1  1.69K_0402_1%  [R_0402]  91.74 128.16 270 top
RV2  1K_0402_1%  [R_0402]  87.37 139.67 270 top
RV3  1K_0402_1%  [R_0402]  92.75 128.16 270 top
RV4  100K_0402_5%  [R_0402]  103.28 126.09 270 bottom
RV5  47K_0402_5%  [R_0402]  90.56 147.33 270 top
RV6  47K_0402_5%  [R_0402]  88.26 145.49 0 top
RV8  8.45K_0402_1%  [R_0402]  97.24 133.03 270 top
RV9  2K_0402_1%  [R_0402]  96.39 132.12 90 top
RV11  8.45K_0402_1%  [R_0402]  99.04 130.68 90 top
RV12  2K_0402_1%  [R_0402]  98.14 131.58 270 top
RV13  4.75K_0402_1%  [R_0402]  99.04 133.75 270 top
RV15  8.45K_0402_1%  [R_0402]  103.11 128.57 0 bottom
RV16  4.75K_0402_1%  [R_0402]  103.14 129.48 0 bottom
RV17  1K_0402_5%  [R_0402]  84.1 146.86 270 top
RV20  1M_0402_5%  [R_0402]  103.22 121.56 90 bottom
RV21  10K_0402_5%  [R_0402]  89.69 148.76 270 bottom
RV28  8.45K_0402_1%  [R_0402]  100.11 132.5 90 top
RV29  10K_0402_5%  [R_0402]  94.8 127.49 90 top
RV31  0_0805_5%  [R0805_0OHM]  92.51 123.92 180 top
RV32  40.2_0402_1%  [R_0402]  88.29 119.74 270 bottom
RV33  40.2_0402_1%  [R_0402]  89.11 119.73 0 bottom
RV34  100_0402_1%  [R_0402]  90.82 119.73 0 bottom
RV35  100_0402_1%  [R_0402]  87.47 119.04 270 bottom
RV36  49.9_0402_1%  [R_0402]  77.29 151.03 0 top
RV37  10_0402_1%  [R_0402]  80.75 150.21 180 top
RV38  5.1K_0402_1%  [R_0402]  80.74 151.02 90 top
RV39  120_0402_1%  [R_0402]  84.48 122.26 90 top
RV40  51.1_0402_1%  [R_0402]  83.28 146.86 270 top
RV41  51.1_0402_1%  [R_0402]  84.09 147.73 0 top
RV42  680_0603_5%  [R_0603]  101.5 105.82 180 top
RV43  3.4K_0402_1%  [R_0402]  99.57 102.93 270 top
RV44  20K_0402_5%  [R_0402]  96.42 105.45 270 top
RV45  470_0603_5%  [R_0603]  83.78 106.46 180 top
RV56  470_0603_5%  [R_0603]  84.93 111.41 0 top
RV57  470_0603_5%  [R_0603]  84.93 112.68 0 top
RV59  10K_0402_5%  [R_0402]  93.74 127.26 90 top
RV79  60.4_0402_1%  [R_0402]  58.26 117.68 90 top
RV80  60.4_0402_1%  [R_0402]  57.43 117.68 90 top
RV81  4.7K_0402_5%  [R_0402]  91.34 147.85 90 bottom
RV82  4.7K_0402_5%  [R_0402]  90.52 147.85 90 bottom
RV83  16.2K_0402_1%  [R_0402]  92.74 147.91 90 bottom
RV84  10K_0402_5%  [R_0402]  103.47 143.08 90 top
RV85  60.4_0402_1%  [R_0402]  58.51 151.11 270 top
RV86  60.4_0402_1%  [R_0402]  57.69 151.11 270 top
RV87  10K_0402_5%  [R_0402]  105.12 143.08 90 top
RV88  10K_0402_5%  [R_0402]  105.12 140.92 90 top
RV89  10K_0402_5%  [R_0402]  103.47 140.92 90 top
RV90  1K_0402_1%  [R_0402]  87.72 141.81 90 top
RV91  10K_0402_5%  [R_0402]  88.44 143.71 90 top
RV93  0_0402_5%  [R_0402]  105.12 143.08 90 bottom
RV94  0_0402_5%  [R_0402]  103.47 143.08 90 bottom
RV116  1K_0402_1%  [R_0402]  57.99 133.44 0 bottom
RV117  1K_0402_1%  [R_0402]  57.99 135.22 0 bottom
RV118  1K_0402_1%  [R_0402]  49.51 124.93 180 bottom
RV119  1K_0402_1%  [R_0402]  49.49 142.41 270 bottom
RV120  121_0402_1%  [R_0402]  56.86 118.41 270 bottom
RV121  121_0402_1%  [R_0402]  59.46 150.64 90 bottom
RV151  10K_0402_5%  [R_0402]  87.53 148.76 270 bottom
RV152  10K_0402_5%  [R_0402]  88.36 147.85 90 bottom
RV154  5.11K_0402_5%  [R_0402]  84.93 146.86 270 top
RV155  0_0402_5%  [R0402_0OHM]  105.12 140.92 90 bottom
RV156  0_0402_5%  [R0402_0OHM]  104.29 140.92 90 bottom
RV157  0_0402_5%  [R0402_0OHM]  103.47 140.92 90 bottom
RV162  4.7K_0402_5%  [R_0402]  105.77 127.73 180 bottom
RV163  4.7K_0402_5%  [R_0402]  104.87 128.54 90 bottom
RV195  0_0402_5%  [R0402_0OHM]  85 150.97 180 top
RV369  10K_0402_5%  [R_0402]  83.23 149.45 180 bottom
RV379  5.49K_0402_1%  [R_0402]  57.81 150.64 90 bottom
RV380  2.37K_0402_1%  [R_0402]  56.99 151.55 270 bottom
RV1642  150K_0402_5%  [R_0402]  89.82 107.1 270 top
RV1643  0_0402_5%  [R0402_0OHM]  103.22 124.19 270 bottom
RV1644  10_0402_5%  [R_0402]  95.6 105.45 270 top
RV3151  1K_0402_5%  [R_0402]  82.32 151.19 0 bottom
RV3152  10K_0402_5%  [R_0402]  83.34 151.94 270 top
RV3153  100K_0402_5%  [R_0402]  99.34 37.57 270 bottom
SW1  TAFG1-12WQR4 SPST DIP H3.3 3P  [SW_NTC325-EK1J-A160T_3P]  5.37 37.23 270 top
T1  -  [TPC12]  79.72 56.16 180 bottom
T2  -  [TPC12]  89.6 63.7 0 top
T3  -  [TPC12]  90.95 64.11 0 top
T4  -  [TPC12]  93.94 62.96 0 top
T5  -  [TPC12]  89.18 58.49 0 top
T6  -  [TPC12]  90.1 60.28 0 top
T7  -  [TPC12]  95.49 66.92 0 top
T8  -  [TPC12]  95.52 62.78 0 top
T9  -  [TPC12]  94.85 71.62 0 top
T10  -  [TPC12]  95.89 70.68 0 top
T11  -  [TPC12]  91.26 68.8 180 bottom
T12  -  [TPC12]  90.77 70.52 180 bottom
T13  -  [TPC12]  102.91 58.96 0 top
T14  -  [TPC12]  101.82 59.66 0 top
T15  -  [TPC12]  89.36 65.46 0 top
T16  -  [TPC12]  88.59 62.84 0 top
T18  -  [TPC12]  88.86 68.04 0 top
T19  -  [TPC12]  88.45 64.5 0 top
T26  -  [TPC12]  91.9 47.88 270 top
T28  -  [TPC12]  93.44 45.8 180 top
T31  -  [TPC12]  102.97 54.18 0 top
T60  -  [TPC12]  87.87 65.74 270 top
T61  -  [TPC12]  95.18 50.09 270 top
T201  -  [TPC12]  86.17 139.97 180 top
T202  -  [TPC12]  86.27 138.65 180 top
T203  -  [TPC12]  95.74 140.18 180 top
T204  -  [TPC12]  91.07 139.57 180 top
T205  -  [TPC12]  95.25 141.42 180 top
T206  -  [TPC12]  96.03 138.91 180 top
T207  -  [TPC12]  93.22 139.44 180 top
T208  -  [TPC12]  94.36 142.62 180 top
T209  -  [TPC12]  94.41 139.94 180 top
T210  -  [TPC12]  93.66 143.82 180 top
T211  -  [TPC12]  92.33 140.46 180 top
T212  -  [TPC12]  93.47 141.24 180 top
T213  -  [TPC12]  92.14 141.73 180 top
T214  -  [TPC12]  95.93 147.92 180 bottom
T215  -  [TPC12]  95.15 146.78 180 bottom
T216  -  [TPC12]  90.84 140.84 180 top
T217  -  [TPC12]  92.39 143.25 180 top
T218  -  [TPC12]  94.01 134.45 180 top
T221  -  [TPC12]  94.2 147.73 180 bottom
T222  -  [TPC12]  91.85 146.78 180 bottom
T223  -  [TPC12]  87.72 146.78 180 bottom
T224  -  [TPC12]  89.05 146.78 180 bottom
T4935  -  [TPC12]  102.14 141 180 bottom
TL1  NS892407  [TAIMA_IH-160_24P]  30.83 131.05 270 bottom
TPL1  PAD~D  [TPC12]  39.3 138.55 180 bottom
TPL2  PAD~D  [TPC12]  40.53 138.18 180 bottom
U11  -  [KB9022QD_LQFP128_14X14]  178.33 51.32 180 top
U18  -  [AOZ1336_DFN8_2X2]  89.48 30.75 270 top
U202  EM5203AJ-20 SOT23 5P  [SY6288C20AAC_SOT23-5]  30.07 147.79 270 top
U203  TC7SH08FUF_SSOP5  [MC74VHC1G08DFT2G_SC70-5]  26.32 147.49 270 top
U282  APX8132 SOT-23F 3P  [S-5711ACDL-M3T1S_SOT23-3]  7.82 161.31 90 top
U301  G524B2T11U SOT-23  [SY6288D20AAC_SOT23-5]  19.52 66.95 0 bottom
U381  -  [EM5209VF_DFN14_3X2]  175.88 12.66 270 top
U1895V  -  [EM5209VF_DFN14_3X2]  88.24 108.92 0 top
UA1  ALC3240-VA3-CG_MQFN40_5X5  [ALC3240-CG_MQFN40_5X5-S]  7.35 23.04 0 bottom
UC1  A6-9200E_BGA769  [A6-9200E_BGA_769P-T]  106.47 66.46 180 bottom
UC2  XM25QU64AHIGT SOP 8P  [W25Q64DWSSIG_SO8]  100.16 21.25 270 bottom
UC21  74AUP1G07GW_SC70-5  [SN74LVC1G07DCKR_SC70-5]  92.79 81.71 0 top
UC22  74AUP1G07GW_SC70-5  [SN74LVC1G07DCKR_SC70-5]  77.42 90.94 0 bottom
UC23  MC74VHC1G08DFT2G SC70 5P  [NC7SZ08P5X_NL_SC70-5]  83.15 30.7 270 bottom
UC24  74AUP1G07GW_SC70-5  [SN74LVC1G07DCKR_SC70-5]  113.8 43.23 270 bottom
UC25  AP2138N-1.5TRG1_SOT23-3  [AP2138N-1P5TRG1_SOT23-3]  100.87 30.36 0 top
UC26  -  [AS393MTR-G1_SO8]  148.17 31.19 180 top
UH1  S IC AP2330W-7 SC59 3P PWR SW  [AP2330W-7_SC59-3]  20.6 112.55 180 bottom
UL2  -  [RTL8111GS-CG_QFN32_4X4]  35.15 133.95 180 bottom
UR1  RTS5146-GR_ QFN24_4X4  [RTS5146-GR_QFN24_4X4]  28.62 9.07 180 top
UV1  2160856030-A0_FCBGA631  [2160889018R1_FCBGA_631P-NH_A39]  78.38 144.69 270 bottom
UV2  MC74VHC1G08DFT2G_SC70-5  [SN74AHC1G08DCKR_SC70-5]  105.58 124.55 180 bottom
UV7  -  [K4G80325FB-HC03_FBGA_170P_A39]  51.58 131.09 270 bottom
UV8  -  [K4G80325FB-HC03_FBGA_170P_A39]  64.38 137.53 90 bottom
VSS_SENSE1  -  [TPC12]  94.07 49.32 270 top
YC32  32.768KHZ_9PF_X1A000141000200  [Y_X1A000141000200_2P]  112.11 37.52 90 bottom
YC48  48MHZ_8PF_7V48000010  [Y_X3S048000D81H-W_4P]  114.61 65.84 270 bottom
YL1  25MHZ_20PF_XRCGB25M000F2P18R0  [Y_XRCGB25M000F2P18R0_4P]  40.53 136.85 270 bottom
YV2  27MHZ_10PF_XRCGB27M000F2P18R0  [Y_XRCGB27M000F2P18R0_4P]  105.24 121.86 270 bottom

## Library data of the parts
C179 C182 C183 C189-C191 C201 C216 C233-C237 C243 C281 C282 C303 C823 C831 C833-C838 C847 C848 C853 C854 C860 C2148 C2150 C2151 C2153 CA1 CA40 CA43 CA45 CA47 CA50-CA52 CA56 CA59 CA61 CA63-CA67 CA71 CC7 CC9 CC11-CC13 CC15 CC16 CC18 CC31-CC43 CC47 CC52 CC54 CC57 CC63 CC68 CC69 CC71-CC76 CC104-CC115 CC129-CC131 CC134 CC135 CC162 CD202 CD207 CD211 CD231 CL13 CL14 CL18 CL20 CL21 CR2 CR3 CR6 CV1-CV8 CV11 CV15 CV17 CV18 CV28 CV29 CV36 CV40-CV42 CV47 CV48 CV96 CV97 CV174-CV179 CV271 CV281 PC101-PC104 PC201 PC202 PC401-PC404 PC412 PC413 PC416-PC419 PC426 PC428 PC451 PC501 PC502 PC505 PC508 PC515-PC519 PC601-PC605 PC608 PC613 PC614 PC705 PC708 PC715 PC747 PC748 PC751 PC752 PC765 PC767-PC769 PC779 PC801 PC804-PC819 PC822 PC825-PC828 PC831-PC837 PC901-PC905 PC907 PC912 PC913 PC943 PC944 PC986-PC988 PC1001-PC1040 PC1042 PC2001-PC2006 PC9064 PC9065 PC9082 PC11214 PC11215 PC11217 PC11227 = C_0402
C180 C181 C184 C187 C193 C202 C204 C206-C211 C217 C232 C239 C244 C271 C272 C275 C280 C301 C302 C305 C832 C839 C840 C843 C846 C849 C852 C855 C858 C859 C861 C2147 C2152 C2154 C2155 CA44 CA46 CA48 CA49 CA53-CA55 CA57 CA58 CA60 CA62 CA68-CA70 CC1-CC4 CC8 CC10 CC14 CC19 CC48-CC50 CC61 CD201 CD205 CD206 CD208 CD210 CD212 CD213 CD222-CD229 CH11-CH20 CL1-CL8 CL10-CL12 CL15 CR1 CR4 CR5 CR7 CV20 CV21 CV26 CV31-CV33 CV37 CV39 CV46 CV49-CV53 CV56-CV60 CV62-CV66 CV80 CV82 CV83 CV85 CV86 CV90 CV92-CV95 CV98 CV99 CV120 CV121 CV124 CV161-CV167 CV169-CV173 CV181 CV187 CV188 CV291 CV301 CV374-CV380 CV382-CV389 CV391 CV392 CV1380 PC429 = C_0201
C203 C238 C371 C844 C845 C850 C851 C856 C857 C2149 CC20-CC30 CC44-CC46 CC51 CC53 CC55 CC56 CC58-CC60 CC62 CC64-CC67 CC70 CC132 CC133 CD203 CD204 CD214-CD221 CL19 CV19 CV27 CV30 CV38 CV43-CV45 CV54 CV55 CV61 CV81 CV84 CV91 CV122 CV123 CV160 CV168 CV373 CV381 PC407-PC411 PC420-PC425 PC427 PC506 PC507 PC509-PC514 PC609-PC612 PC721 PC750 PC757 PC908-PC911 PC1041 PC1043-PC1047 PC1050-PC1053 PC2007-PC2010 PC9001-PC9020 PC9029-PC9031 PC9033 PC9034 PC9038-PC9045 PC9056-PC9060 PC9062 PC9063 PC9067 PC9068 PC9070 PC9071 PC11213 PC11225 PC11226 = C_0603
C205 PC405 PC414 PC415 PC503 PC504 PC606 PC760-PC762 PC775 PC776 PC802 PC803 PC823 PC824 PC906 PC1048 PC1049 PC11216 = C_0805
C304 = C_MP6VLPS220MC4R2
CD230 PC9086 = C_D3
CLRP1 J1 J2 = SHORTPADS: User Part Number: PART#
D1 D303 DA8 DA9 = L03ESDL5V0CC3-2_SOT23-3
D281 = PSOT24C_SOT23-3
D301 D304 DH1-DH3 = YSCLAMP0524P_SLP2510P8-10-9
D302 D305 DA3 DL1 DL2 = AZC099-04SPR7G_SOT23-6
DC3 = RB751V-40TE17_SOD323-2
DL3 = BS4200N-C-LV_SMB-F2
DV1 = CH751H-40PT_SOD323-2
FD1-FD4 = FIDUCIAL_C40M80
H1-H5 = H_3P3
H6-H10 H12 H13 = H_2P5
H11 = H_3P2N
H14 = H_3P5X2P5N
H15 = H_3P2
J4 J5 PJ602 PJ801-PJ804 = JUMP_43X79
JBAT1 = SUYIN_125022HB008M200ZL_8P-T
JDCIN1 = SINGA_2DC3169-000111F_5P-T
JDIMM1 = DEREN_40-42271-26001RHF_260P-T
JEDP1 = ACES_87242-3001-09_30P
JFAN1 = ACES_50271-0040N-001_4P
JHDD1 JODD2 = ACES_51530-01001-P01_10P
JHDMI1 = ACON_HMRA4-AK120C_19P
JHDT1 = SAMTE_ASP-136446-07-B_20P-T
JHP1 = SINGA_2SJ3095-140111F_6P-T
JKB1 = JXT_FP257H-032S10M_32P
JLAN1 = PS_601012-008041_8P
JRTC1 = ACES_50271-0020N-001_2P
JSD1 = DEREN_43-42095-01111RHF-R_11P
JSPK1 = ACES_50278-00401-001_4P
JTP1 = ACES_51522-00601-001_6P
JUSB1 JUSB2 = ACON_TARAN-9R1391_9P
JWLAN1 = LOTES_APCI0128-P005A_75P
L20 L21 = MURAT_BLM15AX300SN1D_2P
L301 L305 L307 L308 = MURAT_DLM0NSN900HY2D_4P
LA5-LA8 PR771 PR1033 R189 R212 R371 RA6 RA48 RA59 RL1 RL18 = R0603_0OHM
LA9 = MURAT_BLM15PX221SN1D_2P
LED2 LED3 = LED_LTW-C193TS5-C_2P
LED4 = LED_LTST-C191KFKT-2CA_2P
LH1-LH4 = INPAQ_HCM1012GH900BP_4P
LV2-LV4 LV6-LV8 PR401 PR408 PR411 PR508 PR510 PR603 PR606 PR607 PR769 PR770 PR772 PR776 PR777 PR808 PR814 PR824 PR826 PR827 PR829 PR831 PR833 PR838 PR851 PR901 PR1004 PR1005 PR1007 PR1014 PR1018 PR1021 PR1022 PR1024 PR1025 PR2003 PR2005 R204 R207 R243-R248 R250 R275 R276 R278 R283 R428 R922 R923 R929 R932 R937 R940 R950 R951 RA46 RA53 RA60 RA61 RA63-RA66 RC20 RC59 RC64 RC66 RC73 RC111 RC120 RD205-RD207 RD210 RL4-RL7 RR5 RV155-RV157 RV195 RV1643 = R0402_0OHM
PC1054-PC1056 = C_5X4P5
PC9084 PC9088 PC9089 = C_D2
PC9085 = C_OVH561M0ETR-0606
PC11224 = C_6P3X6
PD101 = RB715F_SOT323-3
PD501 = D_SOD323-2
PD703 = LRB715FT1G_SOT323-3
PF101 PF201 = F_1206
PH201 PH801-PH804 PH1001 PH1002 PR201-PR206 PR402-PR404 PR406 PR407 PR410 PR412 PR451 PR452 PR502 PR506 PR507 PR509 PR601 PR608-PR612 PR727 PR729 PR731 PR732 PR737 PR738 PR740-PR742 PR745 PR749-PR755 PR757 PR760 PR762 PR763 PR778-PR780 PR801 PR807 PR809-PR813 PR816 PR818 PR820 PR821 PR823 PR825 PR828 PR830 PR832 PR834-PR837 PR839 PR842 PR843 PR845-PR850 PR852 PR853 PR902 PR903 PR905-PR907 PR1001-PR1003 PR1006 PR1008-PR1013 PR1015-PR1017 PR1019 PR1020 PR1023 PR1026-PR1028 PR1098 PR1099 PR1458 PR1459 PR2001 PR2002 PR2004 PR2006-PR2009 PR2221-PR2223 R192 R194 R198 R201 R202 R205 R209 R210 R214 R249 R251 R271-R274 R277 R280 R301 R364-R369 R376-R378 R921 R930 R931 R933 R934 R941 R944 R945 R947-R949 RA23 RA36 RA41 RA43-RA45 RA47 RA49-RA52 RA54-RA58 RA62 RC1-RC4 RC13 RC14 RC16-RC18 RC21 RC22 RC24-RC27 RC30 RC34-RC36 RC38-RC41 RC44-RC46 RC49 RC52-RC54 RC60 RC63 RC69 RC71 RC75-RC90 RC93 RC94 RC100-RC105 RC108 RC112 RC113 RC133 RC134 RC144-RC147 RC150-RC153 RC156-RC164 RD201-RD204 RD208 RD209 RH27-RH30 RH133 RH137 RH138 RL8-RL10 RL17 RR1 RV1-RV6 RV8 RV9 RV11-RV13 RV15-RV17 RV20 RV21 RV28 RV29 RV32-RV41 RV43 RV44 RV59 RV79-RV91 RV93 RV94 RV116-RV121 RV151 RV152 RV154 RV162 RV163 RV369 RV379 RV380 RV1642 RV1644 RV3151-RV3153 = R_0402
PJ401 PJ403 PJ501 PJ502 PJ601 PJ901 PJ902 = JUMP_43X118
PJ503 PJ1000 PJ1001 PJP402 PJP404 = JUMP_43X39
PL101 PL102 PL201 PL202 = TAI-T_HCB2012KF-121T50_2P
PL301 = L_4X4X2_F_2P
PL401 PL403 PL501 = 5A_Z120_0805_2P
PL402 PL404 = L_5X5X3_M
PL502 PL803 PL804 PL1001 = L_7X7X3_M
PL602 PL901 = L_5X5X3_M_2P
PL700 = L_7X7X3_M_2P
PL801 PL802 PL1002 = 5A_Z80_0805_2P
PQ501 PQ704 = AON7408L_DFN8-5
PQ502 = AON7506_DFN3X3-8-5
PQ705 PQ712 = AON7506_DFN33-8-5
PQ706 = AON7752_DFN3X3EP8-5
PQ707 Q84 QH17 QV11 QV17 QV18 = 2N7002KW_SOT323-3
PQ710 = LMUN5113T1G_SOT323-3
PQ711 = LTC015EUBFS8TL_UMT3F
PQ740 = EMB04N03H_EDFN5X6-8-5
PQ741 = L2N7002WT1G_SC70-3
PQ801 PQ803 = AON6380_DFN5X6-8-5
PQ802 PQ804 = Q_N_DFN56-8-5
PQ1001 = AON6962_DFN5X6D-8-7
PR107-PR109 PR501 PR504 PR505 PR803 PR805 PR841 PR1029-PR1032 R935 R946 RL11 RV42 RV45 RV56 RV57 = R_0603
PR405 PR409 PR503 PR605 PR743 PR766 PR804 PR844 PR904 PR1034 = R_1206
PR703 PR765 = R_1206_4P
PR806 RL19 = R_0805
PU401 = SY8286BRAC_QFN20_3X3
PU402 = SY8286CRAC_QFN20_3X3
PU501 = RT8207PGQW_WQFN20_3X3
PU601 = SY8288RAC_QFN20_3X3
PU703 = ISL95520HRZ-T_QFN32_4X4
PU801 = RT3661ABGQW_WQFN40_5X5
PU901 = SY8286RAC_QFN20_3X3
PU903 = APL5336KAI-TRL_SOP8P8
PU1001 = RT3662EBGQW_WQFN32_4X4
PU2001 PU2002 = G9661MF11U_SO8
Q19 = AO4430L_SO8
Q83 = L2N7002WT1G_SC-70-3
Q201 QV16 = PJ2301_SOT23-3
Q401 QV21 = 2N7002KDW_SOT363-6
Q411 Q412 = 2N7002K_SOT23-3
QC1 = LBSS139WT1G_SC70-3
QC2 QC22 = DMN66D0LDW-7_SOT363-6
QC17 = PJT138KA_SOT363-6
QC18-QC21 = AO3416_SOT23-3
QH5 = MMBT3904_NL_SOT23-3
QH15 = 2N7002DW-T-R7_SOT363-6
QV1 = 2N7002KDWH_SOT363-6
R203 R211 R233 R242 R279 R420 RA2 RV31 = R0805_0OHM
RA31 RA42 = MURAT_BLM15BD121SN1D_2P
RC129 RC130 = R0201_0OHM
RP3 RP4 RPC1-RPC6 RPC9 RPC11-RPC14 RPH1 RPH2 RPV34 = RP_0804_8P4R
SW1 = SW_NTC325-EK1J-A160T_3P
T1-T16 T18 T19 T26 T28 T31 T60 T61 T201-T218 T221-T224 T4935 TPL1 TPL2 VSS_SENSE1 = TPC12
TL1 = TAIMA_IH-160_24P
U11 = KB9022QD_LQFP128_14X14
U18 = AOZ1336_DFN8_2X2
U202 = SY6288C20AAC_SOT23-5
U203 = MC74VHC1G08DFT2G_SC70-5
U282 = S-5711ACDL-M3T1S_SOT23-3
U301 = SY6288D20AAC_SOT23-5
U381 U1895V = EM5209VF_DFN14_3X2
UA1 = ALC3240-CG_MQFN40_5X5-S
UC1 = A6-9200E_BGA_769P-T
UC2 = W25Q64DWSSIG_SO8
UC21 UC22 UC24 = SN74LVC1G07DCKR_SC70-5
UC23 = NC7SZ08P5X_NL_SC70-5
UC25 = AP2138N-1P5TRG1_SOT23-3
UC26 = AS393MTR-G1_SO8
UH1 = AP2330W-7_SC59-3
UL2 = RTL8111GS-CG_QFN32_4X4
UR1 = RTS5146-GR_QFN24_4X4
UV1 = 2160889018R1_FCBGA_631P-NH_A39
UV2 = SN74AHC1G08DCKR_SC70-5
UV7 UV8 = K4G80325FB-HC03_FBGA_170P_A39: tolerance: K4G80325FB-HC03_FBGA170~D
YC32 = Y_X1A000141000200_2P
YC48 = Y_X3S048000D81H-W_4P
YL1 = Y_XRCGB25M000F2P18R0_4P
YV2 = Y_XRCGB27M000F2P18R0_4P

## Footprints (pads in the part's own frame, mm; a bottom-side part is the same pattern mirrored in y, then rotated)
2N7002DW-T-R7_SOT363-6
  oval 0.381x1.397 smd: 1(0,0) 2(0.65,0) 3(1.3,0) 4(1.3,1.725) 5(0.65,1.725) 6(0,1.725)
2N7002K_SOT23-3
  oval 1.016x1.524 smd: 1(0,0) 2(0.965,2.083) 3(-0.965,2.083)
2N7002KDW_SOT363-6
  oval 0.356x0.889 smd: 1(0,0) 2(0.65,0) 3(1.3,0) 4(1.3,1.6) 5(0.65,1.6) 6(0,1.6)
2N7002KDWH_SOT363-6
  oval 0.356x0.889 smd: 1(0,0) 2(0.65,0) 3(1.3,0) 4(1.3,1.6) 5(0.65,1.6) 6(0,1.6)
2N7002KW_SOT323-3
  oval 0.66x0.864 smd: 1(0,0) 2(0.65,1.85) 3(-0.65,1.85)
5A_Z80_0805_2P
  rect 0.813x1.397 smd: 1(0,0) 2(1.702,0)
5A_Z120_0805_2P
  rect 0.813x1.397 smd: 1(0,0) 2(1.702,0)
2160889018R1_FCBGA_631P-NH_A39
  round 0.508 smd: A3(0.8,0) A30(20.8,0) A32(21.6,0) AA11(6.4,-14.2) AA12(7.4,-14.2) AA13(8.4,-14.2) AA15(9.4,-14.2) AA16(10.4,-14.2) AA17(11.2,-14.2) AA18(12.2,-14.2) AA20(13.2,-14.2) AA21(14.2,-14.2) AA22(15.2,-14.2) AB11(6.4,-15.2) AB12(7.4,-15.2) AB13(8.4,-15.2) AB15(9.4,-15.2) AB16(10.4,-15.2) AB17(11.2,-15.2) AB18(12.2,-15.2) AB20(13.2,-15.2) AB21(14.2,-15.2) AB22(15.2,-15.2) AK1(0,-20.8) AK3(0.8,-20.8) AK30(20.8,-20.8) AK32(21.6,-20.8) AM1(0,-21.6) AM3(0.8,-21.6) AM30(20.8,-21.6) AM32(21.6,-21.6) C1(0,-0.8) C3(0.8,-0.8) C30(20.8,-0.8) C32(21.6,-0.8) L11(6.4,-6.4) L12(7.4,-6.4) L13(8.4,-6.4) L15(9.4,-6.4) L16(10.4,-6.4) L17(11.2,-6.4) L18(12.2,-6.4) L20(13.2,-6.4) L21(14.2,-6.4) L22(15.2,-6.4) M11(6.4,-7.4) M12(7.4,-7.4) M13(8.4,-7.4) M15(9.4,-7.4) M16(10.4,-7.4) M17(11.2,-7.4) M18(12.2,-7.4) M20(13.2,-7.4) M21(14.2,-7.4) M22(15.2,-7.4) N11(6.4,-8.4) N12(7.4,-8.4) N13(8.4,-8.4) N15(9.4,-8.4) N16(10.4,-8.4) N17(11.2,-8.4) N18(12.2,-8.4) N20(13.2,-8.4) N21(14.2,-8.4) N22(15.2,-8.4) R11(6.4,-9.4) R12(7.4,-9.4) R13(8.4,-9.4) R15(9.4,-9.4) R16(10.4,-9.4) R17(11.2,-9.4) R18(12.2,-9.4) R20(13.2,-9.4) R21(14.2,-9.4) R22(15.2,-9.4) T11(6.4,-10.4) T12(7.4,-10.4) T13(8.4,-10.4) T15(9.4,-10.4) T16(10.4,-10.4) T17(11.2,-10.4) T18(12.2,-10.4) T20(13.2,-10.4) T21(14.2,-10.4) T22(15.2,-10.4) U11(6.4,-11.2) U12(7.4,-11.2) U13(8.4,-11.2) U15(9.4,-11.2) U16(10.4,-11.2) U17(11.2,-11.2) U18(12.2,-11.2) U20(13.2,-11.2) U21(14.2,-11.2) U22(15.2,-11.2) V11(6.4,-12.2) V12(7.4,-12.2) V13(8.4,-12.2) V15(9.4,-12.2) V16(10.4,-12.2) V17(11.2,-12.2) V18(12.2,-12.2) V20(13.2,-12.2) V21(14.2,-12.2) V22(15.2,-12.2) Y11(6.4,-13.2) Y12(7.4,-13.2) Y13(8.4,-13.2) Y15(9.4,-13.2) Y16(10.4,-13.2) Y17(11.2,-13.2) Y18(12.2,-13.2) Y20(13.2,-13.2) Y21(14.2,-13.2) Y22(15.2,-13.2)
  round 0.406 smd: A5(1.6,0) A7(3.2,0) A27(19.2,0) A28(20,0) AB7(3.2,-15) AB8(4,-15) AB9(4.8,-15) AB10(5.6,-15) AB23(16,-15) AB24(16.8,-15) AB25(17.6,-15) AB26(18.4,-15) AC11(6.6,-16) AC13(7.8,-16) AC14(9,-16) AC16(10.2,-16) AC17(11.4,-16) AC19(12.6,-16) AC20(13.8,-16) AC22(15,-16) AD11(6.6,-16.8) AD13(7.8,-16.8) AD14(9,-16.8) AD16(10.2,-16.8) AD17(11.4,-16.8) AD19(12.6,-16.8) AD20(13.8,-16.8) AD22(15,-16.8) AE11(6.6,-17.6) AE13(7.8,-17.6) AE14(9,-17.6) AE16(10.2,-17.6) AE17(11.4,-17.6) AE19(12.6,-17.6) AE20(13.8,-17.6) AE22(15,-17.6) AF2(0.4,-18.4) AF4(1.2,-18.4) AF6(2.4,-18.4) AF7(3.2,-18.4) AF11(6.6,-18.4) AF13(7.8,-18.4) AF14(9,-18.4) AF16(10.2,-18.4) AF17(11.4,-18.4) AF19(12.6,-18.4) AF20(13.8,-18.4) AF22(15,-18.4) AF26(18.4,-18.4) AF27(19.2,-18.4) AF28(20,-18.4) AF30(20.8,-18.4) AF32(21.6,-18.4) AG1(0,-19.2) AG3(0.8,-19.2) AG5(1.6,-19.2) AG6(2.4,-19.2) AG7(3.2,-19.2) AG26(18.4,-19.2) AG27(19.2,-19.2) AG29(20.4,-19.2) AG31(21.2,-19.2) AH1(0,-20) AH3(0.8,-20) AH5(1.6,-20) AH6(2.4,-20) AH26(18.4,-20) AH28(20,-20) AH30(20.8,-20) AH32(21.6,-20) AJ7(3.2,-20.4) AJ27(19.2,-20.4) AK5(1.6,-20.8) AK6(2.4,-20.8) AK26(18.4,-20.8) AK28(20,-20.8) AL7(3.2,-21.2) AL27(19.2,-21.2) AM5(1.6,-21.6) AM6(2.4,-21.6) AM26(18.4,-21.6) AM28(20,-21.6) B6(2.4,-0.4) B26(18.4,-0.4) C5(1.6,-0.8) C7(3.2,-0.8) C27(19.2,-0.8) C28(20,-0.8) D6(2.4,-1.2) D26(18.4,-1.2) E1(0,-1.6) E3(0.8,-1.6) E5(1.6,-1.6) E7(3.2,-1.6) E27(19.2,-1.6) E28(20,-1.6) E30(20.8,-1.6) E32(21.6,-1.6) F2(0.4,-2.4) F4(1.2,-2.4) F6(2.4,-2.4) F7(3.2,-2.4) F26(18.4,-2.4) F27(19.2,-2.4) F28(20,-2.4) F30(20.8,-2.4) F32(21.6,-2.4) G1(0,-3.2) G3(0.8,-3.2) G5(1.6,-3.2) G6(2.4,-3.2) G7(3.2,-3.2) G11(6.6,-3.2) G13(7.8,-3.2) G14(9,-3.2) G16(10.2,-3.2) G17(11.4,-3.2) G19(12.6,-3.2) G20(13.8,-3.2) G22(15,-3.2) G26(18.4,-3.2) G27(19.2,-3.2) G29(20.4,-3.2) G31(21.2,-3.2) H11(6.6,-4) H13(7.8,-4) H14(9,-4) H16(10.2,-4) H17(11.4,-4) H19(12.6,-4) H20(13.8,-4) H22(15,-4) J11(6.6,-4.8) J13(7.8,-4.8) J14(9,-4.8) J16(10.2,-4.8) J17(11.4,-4.8) J19(12.6,-4.8) J20(13.8,-4.8) J22(15,-4.8) K11(6.6,-5.6) K13(7.8,-5.6) K14(9,-5.6) K16(10.2,-5.6) K17(11.4,-5.6) K19(12.6,-5.6) K20(13.8,-5.6) K22(15,-5.6) L7(3.2,-6.6) L8(4,-6.6) L9(4.8,-6.6) L10(5.6,-6.6) L23(16,-6.6) L24(16.8,-6.6) L25(17.6,-6.6) L26(18.4,-6.6) N7(3.2,-7.8) N8(4,-7.8) N9(4.8,-7.8) N10(5.6,-7.8) N23(16,-7.8) N24(16.8,-7.8) N25(17.6,-7.8) N26(18.4,-7.8) P7(3.2,-9) P8(4,-9) P9(4.8,-9) P10(5.6,-9) P23(16,-9) P24(16.8,-9) P25(17.6,-9) P26(18.4,-9) T7(3.2,-10.2) T8(4,-10.2) T9(4.8,-10.2) T10(5.6,-10.2) T23(16,-10.2) T24(16.8,-10.2) T25(17.6,-10.2) T26(18.4,-10.2) U7(3.2,-11.4) U8(4,-11.4) U9(4.8,-11.4) U10(5.6,-11.4) U23(16,-11.4) U24(16.8,-11.4) U25(17.6,-11.4) U26(18.4,-11.4) W7(3.2,-12.6) W8(4,-12.6) W9(4.8,-12.6) W10(5.6,-12.6) W23(16,-12.6) W24(16.8,-12.6) W25(17.6,-12.6) W26(18.4,-12.6) Y7(3.2,-13.8) Y8(4,-13.8) Y9(4.8,-13.8) Y10(5.6,-13.8) Y23(16,-13.8) Y24(16.8,-13.8) Y25(17.6,-13.8) Y26(18.4,-13.8)
  round 0.305 smd: A9(4.8,0) A11(6.4,0) A13(8,0) A15(9.6,0) A17(11.2,0) A19(12.8,0) A21(14.4,0) A23(16,0) A25(17.6,0) AA1(0,-14.4) AA3(0.8,-14.4) AA5(1.6,-14.4) AA6(2.4,-14.4) AA27(19.2,-14.4) AA29(20.4,-14.4) AA31(21.2,-14.4) AB2(0.4,-15.2) AB4(1.2,-15.2) AB6(2.4,-15.2) AB27(19.2,-15.2) AB28(20,-15.2) AB30(20.8,-15.2) AB32(21.6,-15.2) AC1(0,-16) AC3(0.8,-16) AC5(1.6,-16) AC6(2.4,-16) AC7(3.2,-16) AC8(4,-16) AC9(4.8,-16) AC10(5.6,-16) AC23(16,-16) AC24(16.8,-16) AC25(17.6,-16) AC26(18.4,-16) AC27(19.2,-16) AC29(20.4,-16) AC31(21.2,-16) AD2(0.4,-16.8) AD4(1.2,-16.8) AD6(2.4,-16.8) AD7(3.2,-16.8) AD8(4,-16.8) AD9(4.8,-16.8) AD10(5.6,-16.8) AD23(16,-16.8) AD24(16.8,-16.8) AD25(17.6,-16.8) AD26(18.4,-16.8) AD27(19.2,-16.8) AD28(20,-16.8) AD30(20.8,-16.8) AD32(21.6,-16.8) AE1(0,-17.6) AE3(0.8,-17.6) AE5(1.6,-17.6) AE6(2.4,-17.6) AE7(3.2,-17.6) AE8(4,-17.6) AE9(4.8,-17.6) AE10(5.6,-17.6) AE23(16,-17.6) AE24(16.8,-17.6) AE25(17.6,-17.6) AE26(18.4,-17.6) AE27(19.2,-17.6) AE29(20.4,-17.6) AE31(21.2,-17.6) AF8(4,-18.4) AF9(4.8,-18.4) AF10(5.6,-18.4) AF23(16,-18.4) AF24(16.8,-18.4) AF25(17.6,-18.4) AG8(4,-19.2) AG9(4.8,-19.2) AG10(5.6,-19.2) AG11(6.4,-19.2) AG12(7.2,-19.2) AG13(8,-19.2) AG14(8.8,-19.2) AG15(9.6,-19.2) AG16(10.4,-19.2) AG17(11.2,-19.2) AG18(12,-19.2) AG19(12.8,-19.2) AG20(13.6,-19.2) AG21(14.4,-19.2) AG22(15.2,-19.2) AG23(16,-19.2) AG24(16.8,-19.2) AG25(17.6,-19.2) AH8(4,-20) AH10(5.6,-20) AH12(7.2,-20) AH14(8.8,-20) AH16(10.4,-20) AH18(12,-20) AH20(13.6,-20) AH22(15.2,-20) AH24(16.8,-20) AJ9(4.8,-20.4) AJ11(6.4,-20.4) AJ13(8,-20.4) AJ15(9.6,-20.4) AJ17(11.2,-20.4) AJ19(12.8,-20.4) AJ21(14.4,-20.4) AJ23(16,-20.4) AJ25(17.6,-20.4) AK8(4,-20.8) AK10(5.6,-20.8) AK12(7.2,-20.8) AK14(8.8,-20.8) AK16(10.4,-20.8) AK18(12,-20.8) AK20(13.6,-20.8) AK22(15.2,-20.8) AK24(16.8,-20.8) AL9(4.8,-21.2) AL11(6.4,-21.2) AL13(8,-21.2) AL15(9.6,-21.2) AL17(11.2,-21.2) AL19(12.8,-21.2) AL21(14.4,-21.2) AL23(16,-21.2) AL25(17.6,-21.2) AM8(4,-21.6) AM10(5.6,-21.6) AM12(7.2,-21.6) AM14(8.8,-21.6) AM16(10.4,-21.6) AM18(12,-21.6) AM20(13.6,-21.6) AM22(15.2,-21.6) AM24(16.8,-21.6) B8(4,-0.4) B10(5.6,-0.4) B12(7.2,-0.4) B14(8.8,-0.4) B16(10.4,-0.4) B18(12,-0.4) B20(13.6,-0.4) B22(15.2,-0.4) B24(16.8,-0.4) C9(4.8,-0.8) C11(6.4,-0.8) C13(8,-0.8) C15(9.6,-0.8) C17(11.2,-0.8) C19(12.8,-0.8) C21(14.4,-0.8) C23(16,-0.8) C25(17.6,-0.8) D8(4,-1.2) D10(5.6,-1.2) D12(7.2,-1.2) D14(8.8,-1.2) D16(10.4,-1.2) D18(12,-1.2) D20(13.6,-1.2) D22(15.2,-1.2) D24(16.8,-1.2) E9(4.8,-1.6) E11(6.4,-1.6) E13(8,-1.6) E15(9.6,-1.6) E17(11.2,-1.6) E19(12.8,-1.6) E21(14.4,-1.6) E23(16,-1.6) E25(17.6,-1.6) F8(4,-2.4) F9(4.8,-2.4) F10(5.6,-2.4) F11(6.4,-2.4) F12(7.2,-2.4) F13(8,-2.4) F14(8.8,-2.4) F15(9.6,-2.4) F16(10.4,-2.4) F17(11.2,-2.4) F18(12,-2.4) F19(12.8,-2.4) F20(13.6,-2.4) F21(14.4,-2.4) F22(15.2,-2.4) F23(16,-2.4) F24(16.8,-2.4) F25(17.6,-2.4) G8(4,-3.2) G9(4.8,-3.2) G10(5.6,-3.2) G23(16,-3.2) G24(16.8,-3.2) G25(17.6,-3.2) H2(0.4,-4) H4(1.2,-4) H6(2.4,-4) H7(3.2,-4) H8(4,-4) H9(4.8,-4) H10(5.6,-4) H23(16,-4) H24(16.8,-4) H25(17.6,-4) H26(18.4,-4) H27(19.2,-4) H28(20,-4) H30(20.8,-4) H32(21.6,-4) J1(0,-4.8) J3(0.8,-4.8) J5(1.6,-4.8) J6(2.4,-4.8) J7(3.2,-4.8) J8(4,-4.8) J9(4.8,-4.8) J10(5.6,-4.8) J23(16,-4.8) J24(16.8,-4.8) J25(17.6,-4.8) J26(18.4,-4.8) J27(19.2,-4.8) J29(20.4,-4.8) J31(21.2,-4.8) K2(0.4,-5.6) K4(1.2,-5.6) K6(2.4,-5.6) K7(3.2,-5.6) K8(4,-5.6) K9(4.8,-5.6) K10(5.6,-5.6) K23(16,-5.6) K24(16.8,-5.6) K25(17.6,-5.6) K26(18.4,-5.6) K27(19.2,-5.6) K28(20,-5.6) K30(20.8,-5.6) K32(21.6,-5.6) L1(0,-6.4) L3(0.8,-6.4) L5(1.6,-6.4) L6(2.4,-6.4) L27(19.2,-6.4) L29(20.4,-6.4) L31(21.2,-6.4) M2(0.4,-7.2) M4(1.2,-7.2) M6(2.4,-7.2) M27(19.2,-7.2) M28(20,-7.2) M30(20.8,-7.2) M32(21.6,-7.2) N1(0,-8) N3(0.8,-8) N5(1.6,-8) N6(2.4,-8) N27(19.2,-8) N29(20.4,-8) N31(21.2,-8) P2(0.4,-8.8) P4(1.2,-8.8) P6(2.4,-8.8) P27(19.2,-8.8) P28(20,-8.8) P30(20.8,-8.8) P32(21.6,-8.8) R1(0,-9.6) R3(0.8,-9.6) R5(1.6,-9.6) R6(2.4,-9.6) R27(19.2,-9.6) R29(20.4,-9.6) R31(21.2,-9.6) T2(0.4,-10.4) T4(1.2,-10.4) T6(2.4,-10.4) T27(19.2,-10.4) T28(20,-10.4) T30(20.8,-10.4) T32(21.6,-10.4) U1(0,-11.2) U3(0.8,-11.2) U5(1.6,-11.2) U6(2.4,-11.2) U27(19.2,-11.2) U29(20.4,-11.2) U31(21.2,-11.2) V2(0.4,-12) V4(1.2,-12) V6(2.4,-12) V27(19.2,-12) V28(20,-12) V30(20.8,-12) V32(21.6,-12) W1(0,-12.8) W3(0.8,-12.8) W5(1.6,-12.8) W6(2.4,-12.8) W27(19.2,-12.8) W29(20.4,-12.8) W31(21.2,-12.8) Y2(0.4,-13.6) Y4(1.2,-13.6) Y6(2.4,-13.6) Y27(19.2,-13.6) Y28(20,-13.6) Y30(20.8,-13.6) Y32(21.6,-13.6)
